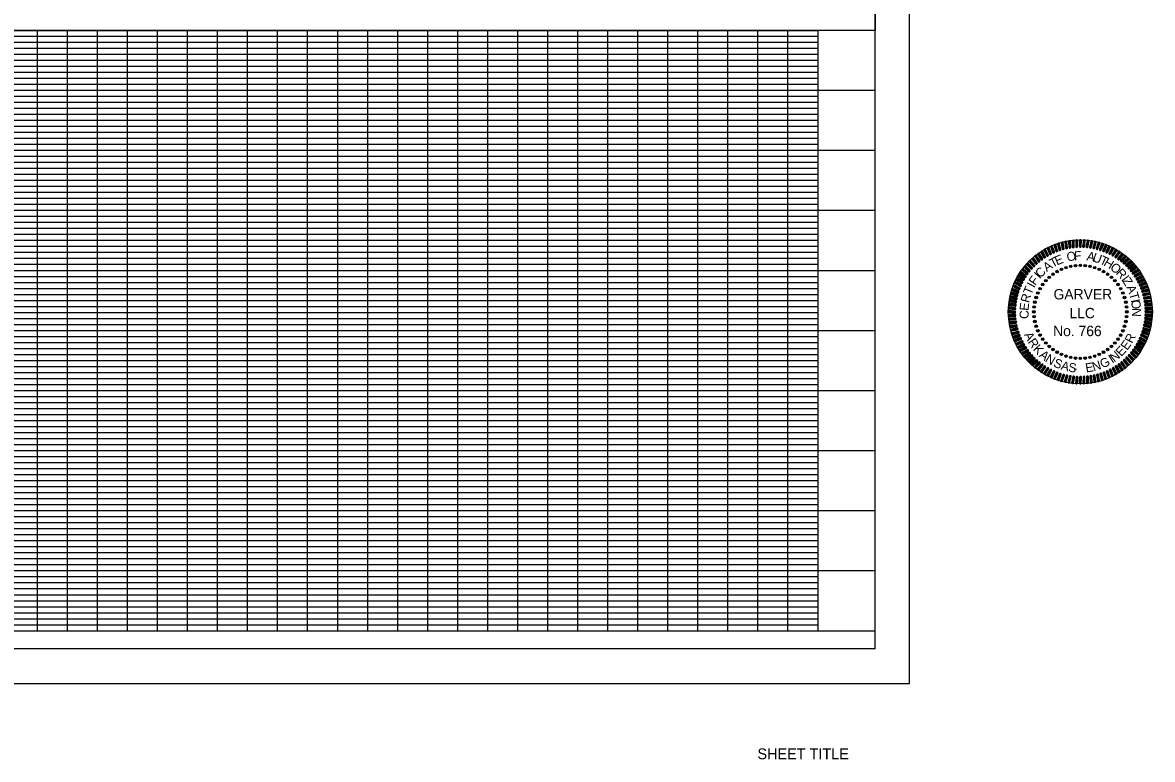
# Model space of a CAD drawing. Extents: x 759422 to 1467391, y 1662254 to 1691810.
# Drawn here: x 1466449 to 1467391, y 1690623 to 1691236 of the extents above; entities that cross this region are included whole.
import ezdxf

# ---------------------------------------------------------------- set-up
doc = ezdxf.new("R2010")
doc.units = 0
for name, color, linetype in [('G-ANNO-STMP', 7, 'Continuous'), ('G-ANNO-TEXT', 7, 'Continuous'), ('G-Border-Paper', 7, 'Continuous'), ('G-Border-Sheet', 7, 'Continuous'), ('G-Grid-Border', 7, 'Continuous'), ('G-Grid-Major', 7, 'Continuous'), ('G-Grid-Minor', 7, 'Continuous'), ('G-No Plot-Border-1', 7, 'Continuous'), ('G-No Plot-Stamp-1', 7, 'Continuous')]:
    doc.layers.add(name, color=color, linetype=linetype)

# ---------------------------------------------------------------- blocks, each defined once
blk = doc.blocks.new('SEALDO')
at = {"layer": 'G-ANNO-TEXT'}
for radius in [0.0396, 0.0305, 0.0213, 0.0122, 0.00305]:
    blk.add_circle((1.403, -0.456), radius, dxfattribs=at)
blk = doc.blocks.new('SEALRI')
at = {"layer": 'G-ANNO-TEXT'}
for p, q in [((-0.023, 2.258), (-0.038, 2.081)), ((-0.008, 2.281), (-0.028, 2.056)), ((0.004, 2.286), (-0.016, 2.049)), ((0.016, 2.285), (-0.004, 2.048)), ((0.028, 2.278), (0.008, 2.052)), ((0.023, 2.076), (0.038, 2.253))]:
    blk.add_line(p, q, dxfattribs=at)
for centre, start, end in [((0.008, 2.256), 355, 175), ((-0.008, 2.078), 175, 355)]:
    blk.add_arc(centre, 0.0305, start, end, dxfattribs=at)

msp = doc.modelspace()

# ---------------------------------------------------------------- linework, layer by layer
at = {"layer": 'G-Border-Paper'}
msp.add_lwpolyline([(1467188.26, 1691786.2), (1465488.26, 1691786.2), (1465488.26, 1690686.2), (1467188.26, 1690686.2)], close=True, dxfattribs=at)
at = {"layer": 'G-Border-Sheet'}
for q in [(1467159.42, 1691757.36), (1465564.06, 1690715.04)]:
    msp.add_line((1467159.42, 1690715.04), q, dxfattribs=at)
at = {"layer": 'G-Grid-Border'}
for p, q in [((1467159.42, 1691229.74), (1465564.06, 1691229.74)), ((1467159.42, 1690729.74), (1465564.06, 1690729.74))]:
    msp.add_line(p, q, dxfattribs=at)
msp.add_lwpolyline([(1465611.74, 1691229.74), (1467111.74, 1691229.74), (1467111.74, 1690729.74), (1465611.74, 1690729.74)], close=True, dxfattribs=at)
at = {"layer": 'G-Grid-Major'}
for p, q in [((1466461.74, 1690729.74), (1466461.74, 1691229.74)), ((1466511.74, 1690729.74), (1466511.74, 1691229.74)), ((1466561.74, 1690729.74), (1466561.74, 1691229.74)), ((1466611.74, 1690729.74), (1466611.74, 1691229.74)), ((1466661.74, 1690729.74), (1466661.74, 1691229.74)), ((1466711.74, 1690729.74), (1466711.74, 1691229.74)), ((1466761.74, 1690729.74), (1466761.74, 1691229.74)), ((1466811.74, 1690729.74), (1466811.74, 1691229.74)), ((1466861.74, 1690729.74), (1466861.74, 1691229.74)), ((1466911.74, 1690729.74), (1466911.74, 1691229.74)), ((1466961.74, 1690729.74), (1466961.74, 1691229.74)), ((1467011.74, 1690729.74), (1467011.74, 1691229.74)), ((1467061.74, 1690729.74), (1467061.74, 1691229.74)), ((1467159.42, 1691179.74), (1465564.06, 1691179.74)), ((1467159.42, 1691129.74), (1465564.06, 1691129.74)), ((1467159.42, 1691079.74), (1465564.06, 1691079.74)), ((1467159.42, 1691029.74), (1465564.06, 1691029.74)), ((1467159.42, 1690979.74), (1465564.06, 1690979.74)), ((1467159.42, 1690929.74), (1465564.06, 1690929.74)), ((1467159.42, 1690879.74), (1465564.06, 1690879.74)), ((1467159.42, 1690829.74), (1465564.06, 1690829.74)), ((1467159.42, 1690779.74), (1465564.06, 1690779.74))]:
    msp.add_line(p, q, dxfattribs=at)
msp.add_lwpolyline([(1465611.74, 1691229.74), (1467111.74, 1691229.74), (1467111.74, 1690729.74), (1465611.74, 1690729.74)], close=True, dxfattribs=at)
at = {"layer": 'G-Grid-Minor'}
for p, q in [((1467111.74, 1691224.74), (1465611.74, 1691224.74)), ((1466486.74, 1690729.74), (1466486.74, 1691229.74)), ((1466536.74, 1690729.74), (1466536.74, 1691229.74)), ((1466586.74, 1690729.74), (1466586.74, 1691229.74)), ((1466636.74, 1690729.74), (1466636.74, 1691229.74)), ((1466686.74, 1690729.74), (1466686.74, 1691229.74)), ((1466736.74, 1690729.74), (1466736.74, 1691229.74)), ((1466786.74, 1690729.74), (1466786.74, 1691229.74)), ((1466836.74, 1690729.74), (1466836.74, 1691229.74)), ((1466886.74, 1690729.74), (1466886.74, 1691229.74)), ((1466936.74, 1690729.74), (1466936.74, 1691229.74)), ((1466986.74, 1690729.74), (1466986.74, 1691229.74)), ((1467036.74, 1690729.74), (1467036.74, 1691229.74)), ((1467086.74, 1690729.74), (1467086.74, 1691229.74)), ((1467111.74, 1691219.74), (1465611.74, 1691219.74)), ((1467111.74, 1691214.74), (1465611.74, 1691214.74)), ((1467111.74, 1691209.74), (1465611.74, 1691209.74)), ((1467111.74, 1691204.74), (1465611.74, 1691204.74)), ((1467111.74, 1691199.74), (1465611.74, 1691199.74)), ((1467111.74, 1691194.74), (1465611.74, 1691194.74)), ((1467111.74, 1691189.74), (1465611.74, 1691189.74)), ((1467111.74, 1691184.74), (1465611.74, 1691184.74)), ((1467111.74, 1691174.74), (1465611.74, 1691174.74)), ((1467111.74, 1691169.74), (1465611.74, 1691169.74)), ((1467111.74, 1691164.74), (1465611.74, 1691164.74)), ((1467111.74, 1691159.74), (1465611.74, 1691159.74)), ((1467111.74, 1691154.74), (1465611.74, 1691154.74)), ((1467111.74, 1691149.74), (1465611.74, 1691149.74)), ((1467111.74, 1691144.74), (1465611.74, 1691144.74)), ((1467111.74, 1691139.74), (1465611.74, 1691139.74)), ((1467111.74, 1691134.74), (1465611.74, 1691134.74)), ((1467111.74, 1691124.74), (1465611.74, 1691124.74)), ((1467111.74, 1691119.74), (1465611.74, 1691119.74)), ((1467111.74, 1691114.74), (1465611.74, 1691114.74)), ((1467111.74, 1691109.74), (1465611.74, 1691109.74)), ((1467111.74, 1691104.74), (1465611.74, 1691104.74)), ((1467111.74, 1691099.74), (1465611.74, 1691099.74)), ((1467111.74, 1691094.74), (1465611.74, 1691094.74)), ((1467111.74, 1691089.74), (1465611.74, 1691089.74)), ((1467111.74, 1691084.74), (1465611.74, 1691084.74)), ((1467111.74, 1691074.74), (1465611.74, 1691074.74)), ((1467111.74, 1691069.74), (1465611.74, 1691069.74)), ((1467111.74, 1691064.74), (1465611.74, 1691064.74)), ((1467111.74, 1691059.74), (1465611.74, 1691059.74)), ((1467111.74, 1691054.74), (1465611.74, 1691054.74)), ((1467111.74, 1691049.74), (1465611.74, 1691049.74)), ((1467111.74, 1691044.74), (1465611.74, 1691044.74)), ((1467111.74, 1691039.74), (1465611.74, 1691039.74)), ((1467111.74, 1691034.74), (1465611.74, 1691034.74)), ((1467111.74, 1691024.74), (1465611.74, 1691024.74)), ((1467111.74, 1691019.74), (1465611.74, 1691019.74)), ((1467111.74, 1691014.74), (1465611.74, 1691014.74)), ((1467111.74, 1691009.74), (1465611.74, 1691009.74)), ((1467111.74, 1691004.74), (1465611.74, 1691004.74)), ((1467111.74, 1690999.74), (1465611.74, 1690999.74)), ((1467111.74, 1690994.74), (1465611.74, 1690994.74)), ((1467111.74, 1690989.74), (1465611.74, 1690989.74)), ((1467111.74, 1690984.74), (1465611.74, 1690984.74)), ((1467111.74, 1690974.74), (1465611.74, 1690974.74)), ((1467111.74, 1690969.74), (1465611.74, 1690969.74)), ((1467111.74, 1690964.74), (1465611.74, 1690964.74)), ((1467111.74, 1690959.74), (1465611.74, 1690959.74)), ((1467111.74, 1690954.74), (1465611.74, 1690954.74)), ((1467111.74, 1690949.74), (1465611.74, 1690949.74)), ((1467111.74, 1690944.74), (1465611.74, 1690944.74)), ((1467111.74, 1690939.74), (1465611.74, 1690939.74)), ((1467111.74, 1690934.74), (1465611.74, 1690934.74)), ((1467111.74, 1690924.74), (1465611.74, 1690924.74)), ((1467111.74, 1690919.74), (1465611.74, 1690919.74)), ((1467111.74, 1690914.74), (1465611.74, 1690914.74)), ((1467111.74, 1690909.74), (1465611.74, 1690909.74)), ((1467111.74, 1690904.74), (1465611.74, 1690904.74)), ((1467111.74, 1690899.74), (1465611.74, 1690899.74)), ((1467111.74, 1690894.74), (1465611.74, 1690894.74)), ((1467111.74, 1690889.74), (1465611.74, 1690889.74)), ((1467111.74, 1690884.74), (1465611.74, 1690884.74)), ((1467111.74, 1690874.74), (1465611.74, 1690874.74)), ((1467111.74, 1690869.74), (1465611.74, 1690869.74)), ((1467111.74, 1690864.74), (1465611.74, 1690864.74)), ((1467111.74, 1690859.74), (1465611.74, 1690859.74)), ((1467111.74, 1690854.74), (1465611.74, 1690854.74)), ((1467111.74, 1690849.74), (1465611.74, 1690849.74)), ((1467111.74, 1690844.74), (1465611.74, 1690844.74)), ((1467111.74, 1690839.74), (1465611.74, 1690839.74)), ((1467111.74, 1690834.74), (1465611.74, 1690834.74)), ((1467111.74, 1690824.74), (1465611.74, 1690824.74)), ((1467111.74, 1690819.74), (1465611.74, 1690819.74)), ((1467111.74, 1690814.74), (1465611.74, 1690814.74)), ((1467111.74, 1690809.74), (1465611.74, 1690809.74)), ((1467111.74, 1690804.74), (1465611.74, 1690804.74)), ((1467111.74, 1690799.74), (1465611.74, 1690799.74)), ((1467111.74, 1690794.74), (1465611.74, 1690794.74)), ((1467111.74, 1690789.74), (1465611.74, 1690789.74)), ((1467111.74, 1690784.74), (1465611.74, 1690784.74)), ((1467111.74, 1690774.74), (1465611.74, 1690774.74)), ((1467111.74, 1690769.74), (1465611.74, 1690769.74)), ((1467111.74, 1690764.74), (1465611.74, 1690764.74)), ((1467111.74, 1690759.74), (1465611.74, 1690759.74)), ((1467111.74, 1690754.74), (1465611.74, 1690754.74)), ((1467111.74, 1690749.74), (1465611.74, 1690749.74)), ((1467111.74, 1690744.74), (1465611.74, 1690744.74)), ((1467111.74, 1690739.74), (1465611.74, 1690739.74)), ((1467111.74, 1690734.74), (1465611.74, 1690734.74))]:
    msp.add_line(p, q, dxfattribs=at)
at = {"layer": 'G-No Plot-Border-1'}
msp.add_lwpolyline([(1465564.06, 1691229.74), (1465564.06, 1691757.36), (1466762.07, 1691757.36), (1466762.07, 1691707.82), (1466960.32, 1691707.82), (1466960.32, 1691692.32), (1467031.92, 1691692.32), (1467031.92, 1691544.82), (1467159.42, 1691544.82), (1467159.42, 1691229.74)], close=True, dxfattribs=at)
at = {"layer": 'G-No Plot-Stamp-1'}
msp.add_circle((1467330.48, 1690995.45), 60, dxfattribs=at)

# ---------------------------------------------------------------- block references
at = {"layer": 'G-ANNO-STMP'}
for name, xscale, yscale, rotation in [('SEALRI', 26.246202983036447, 26.24620298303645, 18), ('SEALRI', 26.24620298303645, 26.24620298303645, 15.000000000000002), ('SEALRI', 26.246202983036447, 26.246202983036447, 12.000000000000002), ('SEALRI', 26.246202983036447, 26.246202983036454, 9), ('SEALRI', 26.246202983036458, 26.246202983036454, 6), ('SEALRI', 26.246202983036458, 26.246202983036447, 3.0000000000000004), ('SEALRI', 26.246202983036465, 26.246202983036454, -2.9999999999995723), ('SEALRI', 26.24620298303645, 26.246202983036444, -5.9999999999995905), ('SEALRI', 26.246202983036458, 26.24620298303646, -8.999999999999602), ('SEALRI', 26.246202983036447, 26.246202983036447, -11.999999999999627), ('SEALRI', 26.24620298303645, 26.246202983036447, -14.999999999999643), ('SEALRI', 26.24620298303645, 26.24620298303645, -17.999999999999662), ('SEALRI', 26.24620298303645, 26.246202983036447, 36), ('SEALRI', 26.24620298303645, 26.246202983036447, 33), ('SEALRI', 26.24620298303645, 26.246202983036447, 30.00000000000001), ('SEALRI', 26.246202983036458, 26.246202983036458, 26.999999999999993), ('SEALRI', 26.246202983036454, 26.24620298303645, 23.99999999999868), ('SEALRI', 26.246202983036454, 26.24620298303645, 20.99999999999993), ('SEALRI', 26.24620298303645, 26.246202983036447, -20.999999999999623), ('SEALRI', 26.246202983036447, 26.24620298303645, -23.99999999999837), ('SEALRI', 26.246202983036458, 26.246202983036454, -26.9999999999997), ('SEALRI', 26.24620298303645, 26.246202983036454, -29.99999999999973), ('SEALRI', 26.24620298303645, 26.246202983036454, -32.999999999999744), ('SEALRI', 26.24620298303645, 26.246202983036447, -35.999999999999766), ('SEALRI', 26.246202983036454, 26.24620298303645, 50.99999999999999), ('SEALRI', 26.246202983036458, 26.246202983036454, 47.99999999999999), ('SEALRI', 26.24620298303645, 26.246202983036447, 44.999999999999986), ('SEALRI', 26.246202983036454, 26.24620298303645, 41.999999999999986), ('SEALRI', 26.246202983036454, 26.24620298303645, 38.999999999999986), ('SEALDO', 26.246202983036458, 26.246202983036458, 125.99999999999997), ('SEALDO', 26.246202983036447, 26.24620298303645, 119.99999999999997), ('SEALDO', 26.24620298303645, 26.246202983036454, 113.99999999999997), ('SEALDO', 26.24620298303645, 26.246202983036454, 107.99999999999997), ('SEALDO', 26.24620298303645, 26.246202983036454, 101.99999999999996), ('SEALDO', 26.246202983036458, 26.246202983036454, 95.99999999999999), ('SEALRI', 26.24620298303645, 26.24620298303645, -38.99999999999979), ('SEALRI', 26.24620298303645, 26.24620298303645, -41.99999999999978), ('SEALRI', 26.246202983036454, 26.24620298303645, -44.99999999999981), ('SEALRI', 26.246202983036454, 26.24620298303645, -47.99999999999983), ('SEALRI', 26.246202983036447, 26.24620298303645, -50.99999999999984), ('SEALRI', 26.246202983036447, 26.24620298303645, 59.999999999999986), ('SEALRI', 26.246202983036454, 26.246202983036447, 56.99999999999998), ('SEALRI', 26.24620298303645, 26.246202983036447, 54), ('SEALDO', 26.246202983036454, 26.24620298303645, 150), ('SEALDO', 26.246202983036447, 26.24620298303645, 144), ('SEALDO', 26.24620298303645, 26.246202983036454, 138), ('SEALDO', 26.246202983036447, 26.246202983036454, 131.99999999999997), ('SEALDO', 26.246202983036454, 26.24620298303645, 90), ('SEALDO', 26.246202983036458, 26.246202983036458, 83.99999999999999), ('SEALDO', 26.246202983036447, 26.24620298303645, 77.99999999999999), ('SEALDO', 26.246202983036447, 26.24620298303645, 72), ('SEALDO', 26.246202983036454, 26.24620298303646, 66.00000000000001), ('SEALRI', 26.24620298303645, 26.24620298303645, -53.99999999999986), ('SEALRI', 26.24620298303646, 26.246202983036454, -56.999999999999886), ('SEALRI', 26.24620298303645, 26.24620298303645, -59.99999999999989), ('SEALRI', 26.246202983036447, 26.24620298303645, 72), ('SEALRI', 26.246202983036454, 26.24620298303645, 68.99999999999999), ('SEALRI', 26.246202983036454, 26.24620298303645, 65.99999999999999), ('SEALRI', 26.246202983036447, 26.246202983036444, 63), ('SEALDO', 26.24620298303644, 26.24620298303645, 168.00000000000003), ('SEALDO', 26.246202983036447, 26.246202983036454, 162.00000000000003), ('SEALDO', 26.24620298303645, 26.246202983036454, 156.00000000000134), ('SEALDO', 26.246202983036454, 26.24620298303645, 60.00000000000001), ('SEALDO', 26.24620298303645, 26.246202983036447, 54), ('SEALDO', 26.246202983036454, 26.24620298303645, 48.000000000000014), ('SEALRI', 26.246202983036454, 26.246202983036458, -62.99999999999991), ('SEALRI', 26.246202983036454, 26.24620298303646, -65.99999999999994), ('SEALRI', 26.246202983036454, 26.24620298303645, -68.99999999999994), ('SEALRI', 26.24620298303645, 26.24620298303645, -71.99999999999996), ('SEALRI', 26.246202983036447, 26.246202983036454, 81), ('SEALRI', 26.246202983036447, 26.246202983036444, 78.00000000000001), ('SEALRI', 26.24620298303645, 26.246202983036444, 75.00000000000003), ('SEALDO', 26.246202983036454, 26.24620298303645, -179.99999999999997), ('SEALDO', 26.246202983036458, 26.246202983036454, 174.00000000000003), ('SEALDO', 26.246202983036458, 26.246202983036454, 42.00000000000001), ('SEALDO', 26.24620298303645, 26.246202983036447, 36), ('SEALRI', 26.246202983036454, 26.24620298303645, -74.99999999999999), ('SEALRI', 26.246202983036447, 26.246202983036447, -78), ('SEALRI', 26.246202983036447, 26.246202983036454, -81.00000000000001), ('SEALRI', 26.246202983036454, 26.24620298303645, 90.00000000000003), ('SEALRI', 26.24620298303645, 26.246202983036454, 87.00000000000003), ('SEALRI', 26.246202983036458, 26.246202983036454, 84.00000000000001), ('SEALDO', 26.24620298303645, 26.246202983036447, -161.99999999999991), ('SEALDO', 26.246202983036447, 26.24620298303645, -167.99999999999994), ('SEALDO', 26.24620298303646, 26.246202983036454, -173.99999999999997), ('SEALDO', 26.246202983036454, 26.24620298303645, 29.999999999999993), ('SEALDO', 26.246202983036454, 26.24620298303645, 23.99999999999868), ('SEALDO', 26.246202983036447, 26.24620298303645, 18), ('SEALRI', 26.246202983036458, 26.246202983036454, -84.00000000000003), ('SEALRI', 26.24620298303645, 26.24620298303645, -87.00000000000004), ('SEALRI', 26.246202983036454, 26.24620298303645, -90.00000000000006), ('SEALRI', 26.246202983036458, 26.246202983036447, 93), ('SEALRI', 26.246202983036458, 26.246202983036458, 96.00000000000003), ('SEALRI', 26.246202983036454, 26.246202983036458, 99.00000000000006), ('SEALDO', 26.24620298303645, 26.24620298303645, -156.00000000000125), ('SEALDO', 26.24620298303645, 26.246202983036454, -149.99999999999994), ('SEALDO', 26.246202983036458, 26.246202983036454, 6), ('SEALDO', 26.246202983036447, 26.246202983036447, 12.000000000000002), ('SEALRI', 26.246202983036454, 26.246202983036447, -99.00000000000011), ('SEALRI', 26.24620298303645, 26.246202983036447, -96.0000000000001), ('SEALRI', 26.246202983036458, 26.246202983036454, -93.00000000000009), ('SEALRI', 26.246202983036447, 26.246202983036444, 102.00000000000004), ('SEALRI', 26.246202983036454, 26.24620298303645, 105.00000000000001), ('SEALRI', 26.24620298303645, 26.24620298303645, 108.00000000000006), ('SEALRI', 26.24620298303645, 26.246202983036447, 111.00000000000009), ('SEALDO', 26.246202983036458, 26.246202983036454, -143.99999999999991), ('SEALDO', 26.246202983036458, 26.246202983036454, -137.9999999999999), ('SEALDO', 26.24620298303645, 26.246202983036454, -131.99999999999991), ('SEALDO', 26.246202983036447, 26.246202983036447, -12.000000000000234), ('SEALDO', 26.24620298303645, 26.24620298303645, -6.000000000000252), ('SEALRI', 26.24620298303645, 26.246202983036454, -111.00000000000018), ('SEALRI', 26.246202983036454, 26.246202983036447, -108.00000000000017), ('SEALRI', 26.246202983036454, 26.24620298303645, -105.00000000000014), ('SEALRI', 26.246202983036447, 26.246202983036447, -102.00000000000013), ('SEALRI', 26.246202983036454, 26.246202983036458, 114.00000000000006), ('SEALRI', 26.24620298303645, 26.246202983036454, 117.00000000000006), ('SEALRI', 26.246202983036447, 26.24620298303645, 120.00000000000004), ('SEALDO', 26.24620298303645, 26.246202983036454, -125.9999999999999), ('SEALDO', 26.24620298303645, 26.24620298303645, -119.99999999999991), ('SEALDO', 26.246202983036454, 26.246202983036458, -113.99999999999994), ('SEALDO', 26.24620298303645, 26.246202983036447, -30.00000000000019), ('SEALDO', 26.246202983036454, 26.246202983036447, -23.999999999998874), ('SEALDO', 26.246202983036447, 26.24620298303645, -18.000000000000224), ('SEALRI', 26.24620298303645, 26.24620298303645, -120.00000000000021), ('SEALRI', 26.24620298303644, 26.24620298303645, -117.00000000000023), ('SEALRI', 26.246202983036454, 26.246202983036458, -114.0000000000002), ('SEALRI', 26.24620298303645, 26.246202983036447, 123.00000000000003), ('SEALRI', 26.24620298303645, 26.246202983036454, 126.00000000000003), ('SEALRI', 26.246202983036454, 26.24620298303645, 129.00000000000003), ('SEALRI', 26.24620298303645, 26.24620298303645, 132), ('SEALDO', 26.24620298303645, 26.24620298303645, -107.99999999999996), ('SEALDO', 26.246202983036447, 26.246202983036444, -101.99999999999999), ('SEALDO', 26.246202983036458, 26.246202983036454, -96), ('SEALDO', 26.246202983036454, 26.24620298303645, -90.00000000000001), ('SEALDO', 26.246202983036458, 26.246202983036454, -84.00000000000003), ('SEALDO', 26.246202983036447, 26.246202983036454, -66.00000000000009), ('SEALDO', 26.24620298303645, 26.246202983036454, -60.0000000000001), ('SEALDO', 26.24620298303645, 26.24620298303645, -54.000000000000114), ('SEALDO', 26.246202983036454, 26.246202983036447, -48.00000000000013), ('SEALDO', 26.24620298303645, 26.246202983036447, -42.00000000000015), ('SEALDO', 26.24620298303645, 26.24620298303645, -36.00000000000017), ('SEALRI', 26.246202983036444, 26.24620298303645, -132.00000000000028), ('SEALRI', 26.246202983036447, 26.24620298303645, -129.00000000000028), ('SEALRI', 26.24620298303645, 26.24620298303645, -126.00000000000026), ('SEALRI', 26.246202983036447, 26.246202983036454, -123.00000000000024), ('SEALRI', 26.24620298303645, 26.246202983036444, 135), ('SEALRI', 26.24620298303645, 26.246202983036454, 138), ('SEALRI', 26.246202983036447, 26.24620298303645, 140.99999999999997), ('SEALRI', 26.246202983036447, 26.24620298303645, 144), ('SEALRI', 26.24620298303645, 26.246202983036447, 146.99999999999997), ('SEALRI', 26.24620298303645, 26.246202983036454, 149.99999999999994), ('SEALDO', 26.24620298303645, 26.246202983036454, -78.00000000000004), ('SEALDO', 26.24620298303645, 26.246202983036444, -72.00000000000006), ('SEALRI', 26.246202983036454, 26.246202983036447, -150.00000000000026), ('SEALRI', 26.24620298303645, 26.246202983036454, -147.00000000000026), ('SEALRI', 26.246202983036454, 26.246202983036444, -144.00000000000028), ('SEALRI', 26.24620298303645, 26.24620298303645, -141.0000000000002), ('SEALRI', 26.24620298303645, 26.246202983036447, -138.00000000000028), ('SEALRI', 26.246202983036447, 26.24620298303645, -135.00000000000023), ('SEALRI', 26.246202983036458, 26.246202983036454, 152.99999999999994), ('SEALRI', 26.24620298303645, 26.246202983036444, 156.00000000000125), ('SEALRI', 26.24620298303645, 26.24620298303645, 159), ('SEALRI', 26.246202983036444, 26.246202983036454, 161.99999999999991), ('SEALRI', 26.24620298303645, 26.246202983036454, 164.99999999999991), ('SEALRI', 26.246202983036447, 26.246202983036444, 167.99999999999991), ('SEALRI', 26.246202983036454, 26.246202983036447, 170.9999999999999), ('SEALRI', 26.24620298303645, 26.24620298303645, 173.9999999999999), ('SEALRI', 26.246202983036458, 26.246202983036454, 176.9999999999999), ('SEALRI', 26.246202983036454, 26.24620298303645, 179.99999999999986), ('SEALRI', 26.246202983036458, 26.246202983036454, -177.00000000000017), ('SEALRI', 26.24620298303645, 26.246202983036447, -174.00000000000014), ('SEALRI', 26.246202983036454, 26.24620298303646, -171.00000000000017), ('SEALRI', 26.246202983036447, 26.24620298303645, -168.0000000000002), ('SEALRI', 26.24620298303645, 26.246202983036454, -165.0000000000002), ('SEALRI', 26.24620298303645, 26.24620298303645, -162.0000000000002), ('SEALRI', 26.24620298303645, 26.246202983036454, -159.00000000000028), ('SEALRI', 26.246202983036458, 26.246202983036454, -156.00000000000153), ('SEALRI', 26.24620298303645, 26.246202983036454, -153.00000000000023)]:
    msp.add_blockref(name, (1467330.49, 1690995.45), dxfattribs=dict(at, xscale=xscale, yscale=yscale, rotation=rotation))
at = {"layer": 'G-ANNO-STMP', "xscale": 26.246202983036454, "yscale": 26.24620298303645}
for name in ['SEALRI', 'SEALDO']:
    msp.add_blockref(name, (1467330.49, 1690995.45), dxfattribs=at)

# ---------------------------------------------------------------- texts
at = {"layer": 'G-ANNO-STMP'}
for s, rotation, p in [('E', 21.61044, (1467310.93, 1691034.05)), ('O', 8.2771, (1467319.62, 1691037.43)), ('F', 1.61044, (1467325.3, 1691038.4)), ('A', 348.2771, (1467335.33, 1691038.47)), ('U', 341.27715, (1467340.02, 1691037.72)), ('A', 34.94377, (1467302.54, 1691028.48)), ('T', 28.2771, (1467307.31, 1691031.93)), ('T', 334.94377, (1467345.91, 1691035.82)), ('H', 328.2771, (1467349.29, 1691034.48)), ('O', 319.7874, (1467354.71, 1691031.4)), ('F', 54.94377, (1467292.93, 1691016.93)), ('I', 49.74076, (1467296.84, 1691022.42)), ('C', 44.38813, (1467297.22, 1691023.19)), ('R', 311.99331, (1467359.63, 1691027.48)), ('I', 307.00814, (1467364.21, 1691022.33)), ('Z', 301.61044, (1467365.09, 1691021.43)), ('T', 67.43139, (1467289.52, 1691009.09)), ('I', 61.61044, (1467292.04, 1691014.91)), ('A', 292.97516, (1467368.63, 1691015.98)), ('R', 74.94377, (1467287.77, 1691002.49)), ('T', 286.3085, (1467370.98, 1691010.56)), ('I', 281.61044, (1467372.48, 1691005.28)), ('C', 91.88416, (1467287.56, 1690989.67)), ('E', 83.89849, (1467287.23, 1690996.08)), ('O', 276.48226, (1467372.77, 1691005.01)), ('N', 268.2771, (1467373.71, 1690998.68)), ('A', 296.57465, (1467283.4, 1690976.45)), ('R', 63.09594, (1467373.69, 1690968.67)), ('R', 304.61826, (1467286.36, 1690970.28)), ('K', 313.3805, (1467290.57, 1690964)), ('E', 54.73091, (1467369.52, 1690962.92)), ('A', 321.25836, (1467295.64, 1690958.52)), ('N', 329.10994, (1467300.57, 1690954.37)), ('I', 32.97899, (1467357.02, 1690952.32)), ('N', 38.98211, (1467358.76, 1690953.21)), ('E', 46.68075, (1467364.55, 1690957.79)), ('S', 337.62936, (1467307.49, 1690950.16)), ('A', 345.40726, (1467313.81, 1690947.51)), ('S', 352.80457, (1467320.17, 1690945.72)), ('E', 10.06947, (1467335.39, 1690944.91)), ('N', 17.86862, (1467341.67, 1690945.85)), ('G', 26.41319, (1467349.06, 1690948.14)), ('-', 0.83848, (1467324.7, 1690944.74))]:
    msp.add_text(s, height=7.5, rotation=rotation, dxfattribs=at).set_placement(p)
for s, p in [('GARVER', (1467308.19, 1691005.81)), ('LLC', (1467321.4, 1690990.1)), ('No. 766', (1467307.82, 1690975.24))]:
    msp.add_text(s, height=8.64, dxfattribs=at).set_placement(p)
at = {"layer": 'G-ANNO-TEXT'}
msp.add_text('SHEET TITLE', height=9, dxfattribs=at).set_placement((1467061.45, 1690623.02))

doc.saveas('drawing.dxf')
